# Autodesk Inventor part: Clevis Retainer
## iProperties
Shininess: 100.0
Angle Display Precision: 2
Document Length Units: 11269
Document Angle Units: 11279
Document Time Units: 11290
Document Mass Units: 11283
Document Length Units Precision: 3
Document Angle Units Precision: 2
Compacted: True
Created: 2001-09
Part Number: Clevis Retainer
Document SubType Name: Sheet Metal
Designer: Martin Budgell
Density: 0.0
Volumn: 0.0
Area: 0.0
PropertySet Name: Model Information
Control State: 0
Master: False
Checked Out: False
Author: Martin Budgell
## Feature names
1. Loft1
2. Extrusion1
3. Fillet1
4. Fillet2
5. Extrusion2
6. Chamfer1
7. Extrusion3
8. Fillet3
9. Extrusion4
10. Fillet4
11. Fillet5
12. Fillet6
13. Corner Round1
14. Plate1
15. Bend1
